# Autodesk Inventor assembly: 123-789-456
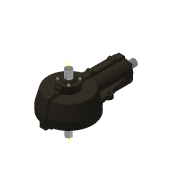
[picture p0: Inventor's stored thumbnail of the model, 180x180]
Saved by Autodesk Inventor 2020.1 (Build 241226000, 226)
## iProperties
Created: 2006-03
Part Number: 123-789-456
Document SubType Name: Assembly
Designer: F.Stasiak
Project: Przekładnia X51
Description: Przekładnia X51
Manager: www.cadconsulting.pl
Company: Fabian Stasiak CAD Consulting
Author: F.Stasiak
Subject: Zbiór ćwiczeń. Autodesk Inventor 2020. Kurs podstawowy
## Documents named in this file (17)
- C:\2020_Kurs_podstawowy\R8 Rysunki\Przekładnia\Przekładnia X51.iam
- C:\2020_Kurs_podstawowy\R8 Rysunki\Przekładnia\123-0050.ipt
- C:\2020_Kurs_podstawowy\R8 Rysunki\Przekładnia\123-0040.ipt
- C:\2020_Kurs_podstawowy\R8 Rysunki\Przekładnia\123-0010.ipt
- C:\2020_Kurs_podstawowy\R8 Rysunki\Przekładnia\123-0080.ipt
- C:\2020_Kurs_podstawowy\R8 Rysunki\Przekładnia\SKF 61907.ipt
- C:\2020_Kurs_podstawowy\R8 Rysunki\Przekładnia\SKF 6005.ipt
- C:\2020_Kurs_podstawowy\R8 Rysunki\Przekładnia\123-0030.ipt
- C:\2020_Kurs_podstawowy\R8 Rysunki\Przekładnia\123-0090.ipt
- C:\2020_Kurs_podstawowy\R8 Rysunki\Przekładnia\pl-PL\DIN 3760 A\22x35x7.ipt
- C:\2020_Kurs_podstawowy\R8 Rysunki\Przekładnia\123-0070.ipt
- C:\2020_Kurs_podstawowy\R8 Rysunki\Przekładnia\pl-PL\DIN 3760 A\25x35x7.ipt
- C:\2020_Kurs_podstawowy\R8 Rysunki\Przekładnia\123-0060.ipt
- C:\2020_Kurs_podstawowy\R8 Rysunki\Przekładnia\123-0020.ipt
- C:\2020_Kurs_podstawowy\R8 Rysunki\Przekładnia\pl-PL\DIN 6885  A\22 - 30-8x7-28.ipt
- C:\2020_Kurs_podstawowy\Zasoby\Content Center Files\pl-PL\ISO 4762(2)\ISO 4762 - M5 x 12ISO.ipt
- C:\2020_Kurs_podstawowy\Zasoby\Content Center Files\pl-PL\DIN 7984\DIN 7984 - M5 x 12.ipt
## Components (26 placed, 16 different names)
1. Wał:1 — Zestawiający:1, Zestawiający:2, Wstaw:1, Równoległy:1, Zestawiający:4, Wstaw:19, Wstaw:20
2. Przekładnie zębate stożkowe 15/51, 3_1:1 — Wstaw:1, Równoległy:1, Wstaw:2
3. 123-0010:1 — Zestawiający:4, Wstaw:4, Wstaw:6, Wstaw:8, Wstaw:11, Wstaw:13, Wstaw:15, Wstaw:16, Kąt:1, Wstaw:17, Wstaw:18, Zestawiający:5
4. 123-0080:1 — Wstaw:2, Wstaw:3
5. Łożysko SKF 61907:1 — Wstaw:6, Zestawiający:10
6. Łożysko SKF 6005:1 — Wstaw:3, Wstaw:4, Zestawiający:7
7. Łożysko SKF 6005:2 — Zestawiający:6
8. Łożysko SKF 61907:2 — Wstaw:10, Wstaw:11, Zestawiający:8
9. Łożysko SKF 6005:3 — Wstaw:8, Wstaw:9, Zestawiający:9
10. Przekładnie zębate stożkowe 15/51, 3:1 — Wstaw:9, Zestawiający:11
11. 123-0090:1 — Wstaw:10
12. DIN 3760 A A - 22 x 35 x 7 - NBR:1 — Wstaw:12
13. 123-0070:1 — Wstaw:12, Wstaw:13
14. 123-0070:2 — Wstaw:14, Wstaw:15, Wstaw:21, Wstaw:22, Wstaw:23, Wstaw:24
15. DIN 3760 A A - 25 x 35 x 7 - NBR:1 — Wstaw:14
16. 123-0060:1 — Wstaw:16, Kąt:1, Wstaw:25, Wstaw:26, Wstaw:27, Wstaw:28
17. 123-0020:1 — Wstaw:17, Wstaw:18
18. DIN 6885  A A 8 x 7 x 28:1 — Wstaw:19, Wstaw:20
19. ISO 4762 M5 x 12:1 — Wstaw:21
20. ISO 4762 M5 x 12:2 — Wstaw:22
21. ISO 4762 M5 x 12:3 — Wstaw:23
22. ISO 4762 M5 x 12:4 — Wstaw:24
23. DIN 7984 M5 x 12:1 — Wstaw:25
24. DIN 7984 M5 x 12:2 — Wstaw:28
25. DIN 7984 M5 x 12:3 — Wstaw:26
26. DIN 7984 M5 x 12:4 — Wstaw:27
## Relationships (38: Insert 26, Mate 10, Flush 1, Angle 1)
- Zestawiający:1 [Mate]: Wał:1
- Zestawiający:2 [Mate]: Wał:1
- Wstaw:1 [Insert]: Wał:1 ↔ Przekładnie zębate stożkowe 15/51, 3_1:1
- Równoległy:1 [Flush]: Wał:1 ↔ Przekładnie zębate stożkowe 15/51, 3_1:1
- Zestawiający:4 [Mate]: Wał:1 ↔ 123-0010:1
- Wstaw:2 [Insert]: Przekładnie zębate stożkowe 15/51, 3_1:1 ↔ 123-0080:1
- Wstaw:3 [Insert]: 123-0080:1 ↔ Łożysko SKF 6005:1
- Wstaw:4 [Insert]: 123-0010:1 ↔ Łożysko SKF 6005:1
- Wstaw:6 [Insert]: 123-0010:1 ↔ Łożysko SKF 61907:1
- Wstaw:8 [Insert]: 123-0010:1 ↔ Łożysko SKF 6005:3
- Wstaw:9 [Insert]: Łożysko SKF 6005:3 ↔ Przekładnie zębate stożkowe 15/51, 3:1
- Wstaw:10 [Insert]: Łożysko SKF 61907:2 ↔ 123-0090:1
- Wstaw:11 [Insert]: 123-0010:1 ↔ Łożysko SKF 61907:2
- Wstaw:12 [Insert]: DIN 3760 A A - 22 x 35 x 7 - NBR:1 ↔ 123-0070:1
- Wstaw:13 [Insert]: 123-0010:1 ↔ 123-0070:1
- Wstaw:14 [Insert]: 123-0070:2 ↔ DIN 3760 A A - 25 x 35 x 7 - NBR:1
- Wstaw:15 [Insert]: 123-0010:1 ↔ 123-0070:2
- Wstaw:16 [Insert]: 123-0010:1 ↔ 123-0060:1
- Kąt:1 [Angle]: 123-0010:1 ↔ 123-0060:1
- Wstaw:17 [Insert]: 123-0010:1 ↔ 123-0020:1
- Wstaw:18 [Insert]: 123-0010:1 ↔ 123-0020:1
- Wstaw:19 [Insert]: Wał:1 ↔ DIN 6885  A A 8 x 7 x 28:1
- Wstaw:20 [Insert]: Wał:1 ↔ DIN 6885  A A 8 x 7 x 28:1
- Zestawiający:5 [Mate]: 123-0010:1
- Zestawiający:6 [Mate]: Łożysko SKF 6005:2
- Zestawiający:7 [Mate]: Łożysko SKF 6005:1
- Zestawiający:8 [Mate]: Łożysko SKF 61907:2
- Zestawiający:9 [Mate]: Łożysko SKF 6005:3
- Zestawiający:10 [Mate]: Łożysko SKF 61907:1
- Zestawiający:11 [Mate]: Przekładnie zębate stożkowe 15/51, 3:1
- Wstaw:21 [Insert]: 123-0070:2 ↔ ISO 4762 M5 x 12:1
- Wstaw:22 [Insert]: 123-0070:2 ↔ ISO 4762 M5 x 12:2
- Wstaw:23 [Insert]: 123-0070:2 ↔ ISO 4762 M5 x 12:3
- Wstaw:24 [Insert]: 123-0070:2 ↔ ISO 4762 M5 x 12:4
- Wstaw:25 [Insert]: 123-0060:1 ↔ DIN 7984 M5 x 12:1
- Wstaw:26 [Insert]: 123-0060:1 ↔ DIN 7984 M5 x 12:3
- Wstaw:27 [Insert]: 123-0060:1 ↔ DIN 7984 M5 x 12:4
- Wstaw:28 [Insert]: 123-0060:1 ↔ DIN 7984 M5 x 12:2
